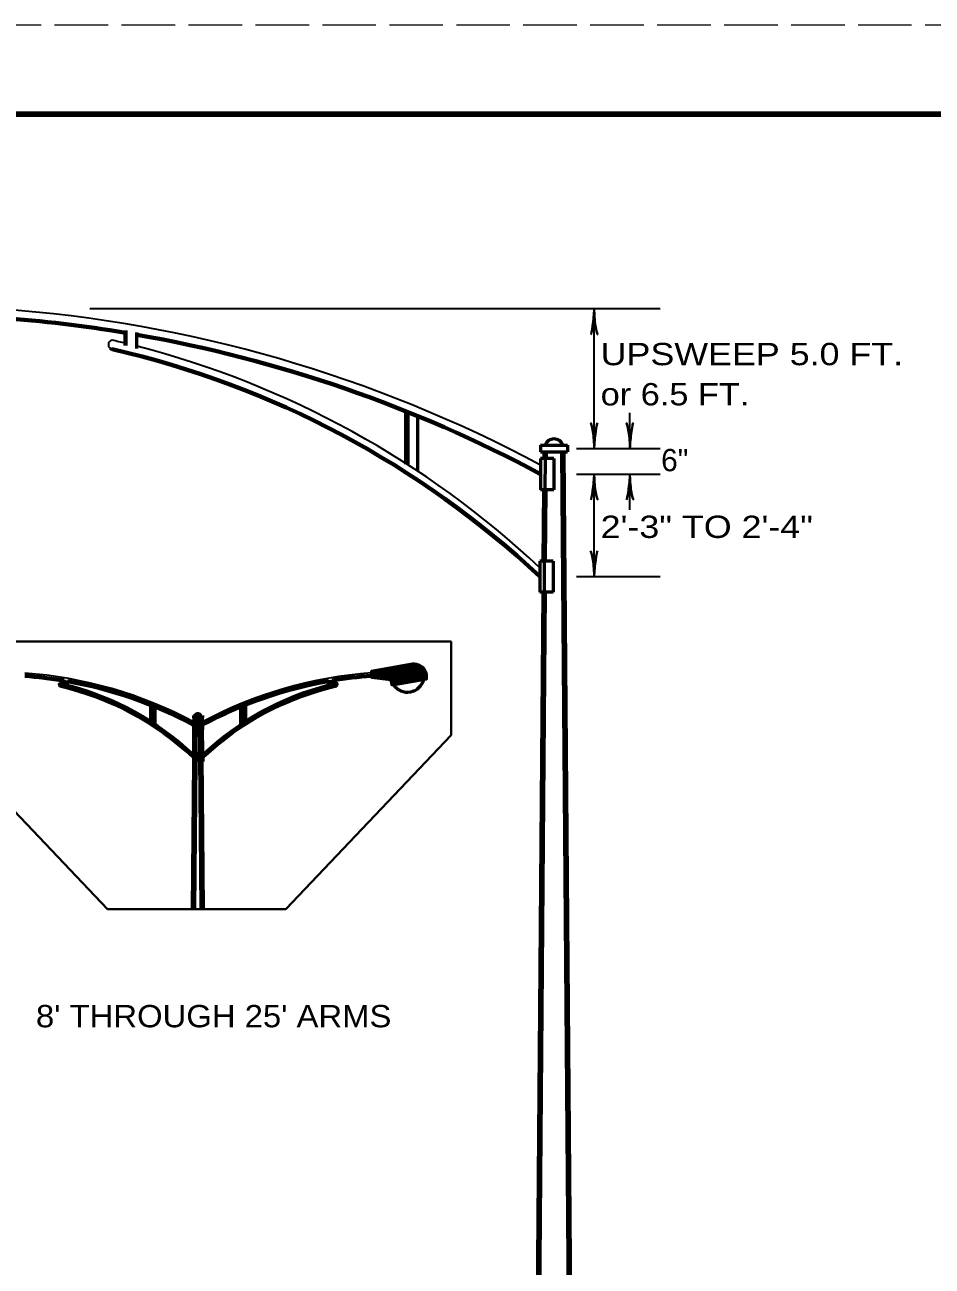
# Model space of a CAD drawing. Extents: x -1 to 679, y 1 to 441.
# Drawn here: x 78.6 to 180.2, y 301.7 to 440.9 of the extents above; entities that cross this region are included whole.
import ezdxf

# ---------------------------------------------------------------- set-up
doc = ezdxf.new("R2010")
doc.units = 0
doc.linetypes.add('LONG_DASHED', pattern=[7.5, 6, -1.5])
doc.layers.add('1', color=7, linetype='Continuous', lineweight=13)
doc.layers.add('61', color=7, linetype='Continuous', lineweight=35)

msp = doc.modelspace()

# ---------------------------------------------------------------- linework, layer by layer
at = {"layer": '1', "lineweight": 35}
for p, q in [((149.714, 409.017), (85.835, 409.017)), ((142.335, 393.392), (142.335, 409.017)), ((146.335, 393.392), (146.335, 397.392)), ((140.335, 393.392), (149.714, 393.392)), ((140.335, 390.517), (149.714, 390.517)), ((142.335, 379.017), (142.335, 390.517)), ((146.335, 386.517), (146.335, 390.517)), ((140.335, 379.017), (149.714, 379.017))]:
    msp.add_line(p, q, dxfattribs=at)
at = {"layer": '1', "lineweight": 70}
for p, q in [((89.835, 404.912), (89.835, 406.601)), ((82.932, 366.924), (82.932, 367.452)), ((113.005, 366.939), (113.005, 367.467))]:
    msp.add_line(p, q, dxfattribs=at)
at = {"layer": '1', "lineweight": 53}
for p, q in [((91.085, 404.598), (91.085, 406.388)), ((122.585, 390.824), (122.585, 397.006)), ((136.335, 393.767), (139.335, 393.767)), ((136.335, 393.767), (136.335, 393.017)), ((139.335, 393.767), (139.335, 393.017)), ((136.335, 393.017), (139.335, 393.017)), ((137.829, 392.267), (136.329, 392.267)), ((136.329, 392.267), (136.329, 388.767)), ((136.829, 392.267), (136.803, 388.767)), ((137.829, 392.267), (137.829, 388.767)), ((137.829, 388.767), (136.329, 388.767)), ((137.742, 380.767), (136.242, 380.767)), ((136.242, 380.767), (136.242, 377.267)), ((136.742, 380.767), (136.716, 377.267)), ((137.742, 380.767), (137.742, 377.267)), ((137.742, 377.267), (136.242, 377.267)), ((119.603, 368.261), (119.17, 368.694)), ((119.647, 368.261), (119.208, 368.701)), ((119.692, 368.261), (119.245, 368.707)), ((119.736, 368.261), (119.283, 368.714)), ((119.78, 368.261), (119.321, 368.721)), ((119.824, 368.261), (119.358, 368.727)), ((119.868, 368.261), (119.396, 368.734)), ((119.913, 368.261), (119.433, 368.74)), ((119.957, 368.261), (119.471, 368.747)), ((120.001, 368.261), (119.508, 368.754)), ((120.045, 368.261), (119.546, 368.76)), ((120.089, 368.261), (119.584, 368.767)), ((120.134, 368.261), (119.621, 368.774)), ((120.178, 368.261), (119.659, 368.78)), ((120.222, 368.261), (119.696, 368.787)), ((120.266, 368.261), (119.734, 368.793)), ((120.31, 368.261), (119.771, 368.8)), ((120.355, 368.261), (119.809, 368.807)), ((120.399, 368.261), (119.847, 368.813)), ((120.443, 368.261), (119.884, 368.82)), ((120.487, 368.261), (119.922, 368.826)), ((120.531, 368.261), (119.959, 368.833)), ((120.576, 368.261), (119.997, 368.84)), ((120.62, 368.261), (120.034, 368.846)), ((120.664, 368.261), (120.072, 368.853)), ((120.708, 368.261), (120.11, 368.86)), ((120.752, 368.261), (120.147, 368.866)), ((120.796, 368.261), (120.185, 368.873)), ((120.841, 368.261), (120.222, 368.879)), ((120.885, 368.261), (120.26, 368.886)), ((120.929, 368.261), (120.297, 368.893)), ((120.973, 368.261), (120.335, 368.899)), ((121.017, 368.261), (120.373, 368.906)), ((121.062, 368.261), (120.41, 368.913)), ((121.106, 368.261), (120.448, 368.919)), ((121.15, 368.261), (120.485, 368.926)), ((121.194, 368.261), (120.523, 368.933)), ((121.239, 368.261), (120.56, 368.939)), ((121.283, 368.261), (120.598, 368.946)), ((121.327, 368.261), (120.636, 368.952)), ((121.371, 368.261), (120.673, 368.959)), ((121.415, 368.261), (120.711, 368.966)), ((121.459, 368.261), (120.748, 368.972)), ((121.504, 368.261), (120.786, 368.979)), ((121.548, 368.261), (120.823, 368.986)), ((121.592, 368.261), (120.861, 368.992)), ((121.636, 368.261), (120.899, 368.999)), ((121.68, 368.261), (120.936, 369.005)), ((121.725, 368.261), (120.974, 369.012)), ((121.769, 368.261), (121.011, 369.019)), ((121.813, 368.261), (121.049, 369.025)), ((121.857, 368.261), (121.086, 369.032)), ((121.901, 368.261), (121.124, 369.038)), ((121.946, 368.261), (121.161, 369.045)), ((121.99, 368.261), (121.199, 369.052)), ((122.034, 368.261), (121.237, 369.058)), ((122.078, 368.261), (121.274, 369.065)), ((122.122, 368.261), (121.312, 369.072)), ((122.167, 368.261), (121.349, 369.078)), ((122.211, 368.261), (121.387, 369.085)), ((122.255, 368.261), (121.424, 369.091)), ((122.299, 368.261), (121.462, 369.098)), ((122.343, 368.261), (121.5, 369.105)), ((122.388, 368.261), (121.537, 369.111)), ((122.432, 368.261), (121.575, 369.118)), ((122.476, 368.261), (121.612, 369.125)), ((122.52, 368.261), (121.65, 369.131)), ((122.564, 368.261), (121.688, 369.138)), ((122.608, 368.261), (121.725, 369.144)), ((122.653, 368.261), (121.763, 369.151)), ((122.697, 368.261), (121.8, 369.158)), ((122.741, 368.261), (121.838, 369.164)), ((122.785, 368.261), (121.875, 369.171)), ((122.829, 368.261), (121.913, 369.178)), ((122.874, 368.261), (121.95, 369.184)), ((122.918, 368.261), (121.988, 369.191)), ((122.962, 368.261), (122.028, 369.195)), ((123.006, 368.261), (122.07, 369.197)), ((123.05, 368.261), (122.114, 369.197)), ((123.095, 368.261), (122.158, 369.198)), ((123.139, 368.261), (122.202, 369.198)), ((123.183, 368.261), (122.251, 369.193)), ((123.227, 368.261), (122.299, 369.189)), ((123.271, 368.261), (122.349, 369.184)), ((123.316, 368.261), (122.404, 369.173)), ((123.529, 368.091), (122.459, 369.162)), ((123.517, 368.148), (122.518, 369.147)), ((123.495, 368.214), (122.582, 369.127)), ((123.473, 368.28), (122.648, 369.105)), ((123.439, 368.358), (122.726, 369.071)), ((123.4, 368.442), (122.813, 369.029)), ((123.336, 368.55), (122.919, 368.966)), ((123.139, 368.791), (123.138, 368.792)), ((83.323, 366.826), (83.323, 367.385)), ((112.614, 366.841), (112.614, 367.4)), ((117.536, 368.207), (117.38, 368.363)), ((118.025, 367.674), (117.38, 368.319)), ((117.974, 367.68), (117.38, 368.275)), ((117.924, 367.686), (117.38, 368.231)), ((117.874, 367.693), (117.38, 368.187)), ((117.823, 367.699), (117.38, 368.142)), ((117.773, 367.705), (117.38, 368.098)), ((117.722, 367.711), (117.38, 368.054)), ((117.672, 367.717), (117.38, 368.01)), ((117.622, 367.724), (117.38, 367.966)), ((117.571, 367.73), (117.38, 367.921)), ((117.521, 367.736), (117.38, 367.877)), ((117.471, 367.742), (117.38, 367.833)), ((117.42, 367.748), (117.38, 367.789)), ((117.536, 368.251), (117.405, 368.383)), ((117.57, 368.261), (117.442, 368.389)), ((117.614, 368.261), (117.48, 368.396)), ((117.659, 368.261), (117.517, 368.402)), ((117.703, 368.261), (117.555, 368.409)), ((118.075, 367.668), (117.56, 368.183)), ((117.747, 368.261), (117.592, 368.416)), ((118.126, 367.662), (117.604, 368.183)), ((117.791, 368.261), (117.63, 368.422)), ((118.176, 367.655), (117.648, 368.183)), ((117.836, 368.261), (117.667, 368.429)), ((118.226, 367.649), (117.693, 368.183)), ((117.88, 368.261), (117.705, 368.436)), ((118.277, 367.643), (117.737, 368.183)), ((117.924, 368.261), (117.743, 368.442)), ((117.968, 368.261), (117.78, 368.449)), ((118.327, 367.637), (117.781, 368.183)), ((118.012, 368.261), (117.818, 368.455)), ((118.377, 367.631), (117.825, 368.183)), ((118.056, 368.261), (117.855, 368.462)), ((118.428, 367.625), (117.869, 368.183)), ((118.101, 368.261), (117.893, 368.469)), ((118.478, 367.618), (117.914, 368.183)), ((118.145, 368.261), (117.931, 368.475)), ((118.529, 367.612), (117.958, 368.183)), ((118.189, 368.261), (117.968, 368.482)), ((118.579, 367.606), (118.002, 368.183)), ((118.233, 368.261), (118.006, 368.489)), ((118.277, 368.261), (118.043, 368.495)), ((118.629, 367.6), (118.046, 368.183)), ((118.322, 368.261), (118.081, 368.502)), ((118.68, 367.594), (118.09, 368.183)), ((118.366, 368.261), (118.118, 368.508)), ((118.73, 367.587), (118.135, 368.183)), ((118.41, 368.261), (118.156, 368.515)), ((118.78, 367.581), (118.179, 368.183)), ((118.454, 368.261), (118.194, 368.522)), ((118.831, 367.575), (118.223, 368.183)), ((118.498, 368.261), (118.231, 368.528)), ((118.881, 367.569), (118.267, 368.183)), ((118.543, 368.261), (118.269, 368.535)), ((118.587, 368.261), (118.306, 368.542)), ((118.932, 367.563), (118.311, 368.183)), ((118.631, 368.261), (118.344, 368.548)), ((118.982, 367.556), (118.356, 368.183)), ((118.675, 368.261), (118.381, 368.555)), ((119.032, 367.55), (118.4, 368.183)), ((118.719, 368.261), (118.419, 368.561)), ((119.083, 367.544), (118.444, 368.183)), ((118.764, 368.261), (118.456, 368.568)), ((119.133, 367.538), (118.488, 368.183)), ((118.808, 368.261), (118.494, 368.575)), ((118.852, 368.261), (118.532, 368.581)), ((119.184, 367.532), (118.532, 368.183)), ((118.896, 368.261), (118.569, 368.588)), ((119.234, 367.525), (118.577, 368.183)), ((118.94, 368.261), (118.607, 368.595)), ((119.284, 367.519), (118.621, 368.183)), ((118.984, 368.261), (118.644, 368.601)), ((119.335, 367.513), (118.665, 368.183)), ((119.029, 368.261), (118.682, 368.608)), ((119.385, 367.507), (118.709, 368.183)), ((119.073, 368.261), (118.719, 368.614)), ((119.435, 367.501), (118.753, 368.183)), ((119.117, 368.261), (118.757, 368.621)), ((119.161, 368.261), (118.795, 368.628)), ((119.486, 367.495), (118.797, 368.183)), ((119.206, 368.261), (118.832, 368.634)), ((119.536, 367.488), (118.842, 368.183)), ((119.25, 368.261), (118.87, 368.641)), ((120.113, 366.956), (118.886, 368.183)), ((119.294, 368.261), (118.907, 368.648)), ((120.15, 366.963), (118.93, 368.183)), ((119.338, 368.261), (118.945, 368.654)), ((120.188, 366.969), (118.974, 368.183)), ((119.382, 368.261), (118.983, 368.661)), ((120.225, 366.976), (119.019, 368.183)), ((119.426, 368.261), (119.02, 368.667)), ((119.471, 368.261), (119.058, 368.674)), ((120.263, 366.983), (119.063, 368.183)), ((119.515, 368.261), (119.095, 368.681)), ((120.301, 366.989), (119.107, 368.183)), ((119.559, 368.261), (119.133, 368.687)), ((120.338, 366.996), (119.151, 368.183)), ((120.376, 367.003), (119.195, 368.183)), ((120.413, 367.009), (119.239, 368.183)), ((120.451, 367.016), (119.284, 368.183)), ((120.488, 367.022), (119.328, 368.183)), ((120.526, 367.029), (119.372, 368.183)), ((120.563, 367.036), (119.416, 368.183)), ((120.601, 367.042), (119.46, 368.183)), ((120.639, 367.049), (119.505, 368.183)), ((120.676, 367.055), (119.549, 368.183)), ((120.075, 366.95), (119.555, 367.47)), ((120.037, 366.943), (119.568, 367.412)), ((120, 366.936), (119.581, 367.355)), ((120.714, 367.062), (119.593, 368.183)), ((119.962, 366.93), (119.594, 367.298)), ((120.751, 367.069), (119.637, 368.183)), ((120.789, 367.075), (119.681, 368.183)), ((120.826, 367.082), (119.726, 368.183)), ((120.864, 367.089), (119.77, 368.183)), ((120.902, 367.095), (119.814, 368.183)), ((120.939, 367.102), (119.858, 368.183)), ((120.977, 367.108), (119.902, 368.183)), ((121.014, 367.115), (119.947, 368.183)), ((121.052, 367.122), (119.991, 368.183)), ((121.089, 367.128), (120.035, 368.183)), ((121.127, 367.135), (120.079, 368.183)), ((121.165, 367.142), (120.123, 368.183)), ((121.202, 367.148), (120.167, 368.183)), ((121.24, 367.155), (120.212, 368.183)), ((121.277, 367.161), (120.256, 368.183)), ((121.315, 367.168), (120.3, 368.183)), ((121.352, 367.175), (120.344, 368.183)), ((121.39, 367.181), (120.388, 368.183)), ((121.427, 367.188), (120.433, 368.183)), ((121.465, 367.195), (120.477, 368.183)), ((121.503, 367.201), (120.521, 368.183)), ((121.54, 367.208), (120.565, 368.183)), ((121.578, 367.215), (120.609, 368.183)), ((121.615, 367.221), (120.654, 368.183)), ((121.653, 367.228), (120.698, 368.183)), ((121.691, 367.234), (120.742, 368.183)), ((121.728, 367.241), (120.786, 368.183)), ((121.766, 367.248), (120.83, 368.183)), ((121.803, 367.254), (120.875, 368.183)), ((121.841, 367.261), (120.919, 368.183)), ((121.878, 367.268), (120.963, 368.183)), ((121.916, 367.274), (121.007, 368.183)), ((121.954, 367.281), (121.051, 368.183)), ((121.991, 367.287), (121.096, 368.183)), ((122.029, 367.294), (121.14, 368.183)), ((122.066, 367.301), (121.184, 368.183)), ((122.104, 367.307), (121.228, 368.183)), ((122.141, 367.314), (121.272, 368.183)), ((122.179, 367.32), (121.317, 368.183)), ((122.216, 367.327), (121.361, 368.183)), ((122.254, 367.334), (121.405, 368.183)), ((122.292, 367.34), (121.449, 368.183)), ((122.329, 367.347), (121.493, 368.183)), ((122.367, 367.354), (121.537, 368.183)), ((122.404, 367.36), (121.582, 368.183)), ((122.442, 367.367), (121.626, 368.183)), ((122.48, 367.373), (121.67, 368.183)), ((122.517, 367.38), (121.714, 368.183)), ((122.555, 367.387), (121.759, 368.183)), ((122.592, 367.393), (121.803, 368.183)), ((122.63, 367.4), (121.847, 368.183)), ((122.667, 367.407), (121.891, 368.183)), ((122.705, 367.413), (121.935, 368.183)), ((122.742, 367.42), (121.98, 368.183)), ((122.78, 367.426), (122.024, 368.183)), ((122.818, 367.433), (122.068, 368.183)), ((122.855, 367.44), (122.112, 368.183)), ((122.893, 367.446), (122.156, 368.183)), ((122.93, 367.453), (122.2, 368.183)), ((122.968, 367.46), (122.245, 368.183)), ((123.005, 367.466), (122.289, 368.183)), ((123.043, 367.473), (122.333, 368.183)), ((123.081, 367.48), (122.377, 368.183)), ((123.118, 367.486), (122.421, 368.183)), ((123.156, 367.493), (122.466, 368.183)), ((123.193, 367.499), (122.51, 368.183)), ((123.231, 367.506), (122.554, 368.183)), ((123.268, 367.513), (122.598, 368.183)), ((123.306, 367.519), (122.642, 368.183)), ((123.344, 367.526), (122.687, 368.183)), ((123.381, 367.533), (122.731, 368.183)), ((123.419, 367.539), (122.775, 368.183)), ((123.456, 367.546), (122.819, 368.183)), ((123.494, 367.552), (122.863, 368.183)), ((123.531, 367.559), (122.907, 368.183)), ((123.554, 367.58), (122.952, 368.183)), ((123.558, 367.621), (122.996, 368.183)), ((123.562, 367.661), (123.04, 368.183)), ((123.566, 367.702), (123.084, 368.183)), ((123.566, 367.745), (123.129, 368.183)), ((123.566, 367.79), (123.173, 368.183)), ((123.565, 367.835), (123.217, 368.183)), ((123.562, 367.881), (123.261, 368.183)), ((123.557, 367.931), (123.305, 368.183)), ((123.542, 368.035), (123.325, 368.252)), ((123.551, 367.981), (123.325, 368.208)), ((119.925, 366.923), (119.608, 367.24)), ((119.887, 366.916), (119.621, 367.183)), ((119.85, 366.91), (119.634, 367.125)), ((119.812, 366.903), (119.647, 367.068)), ((119.774, 366.897), (119.661, 367.01)), ((119.737, 366.89), (119.674, 366.953)), ((119.699, 366.883), (119.687, 366.895)), ((93.167, 362.521), (93.167, 364.453)), ((97.464, 363.441), (98.401, 363.441)), ((97.464, 363.441), (97.464, 363.207)), ((97.464, 363.207), (98.401, 363.207)), ((98.401, 363.441), (98.401, 363.207)), ((98.473, 363.456), (98.473, 363.222)), ((102.77, 362.537), (102.77, 364.469)), ((97.931, 362.972), (97.462, 362.972)), ((97.462, 362.972), (97.462, 361.879)), ((97.931, 361.879), (97.462, 361.879)), ((97.618, 362.972), (97.61, 361.879)), ((97.931, 362.972), (97.931, 361.879)), ((98.006, 362.988), (98.475, 362.988)), ((98.006, 362.988), (98.006, 361.894)), ((98.006, 361.894), (98.475, 361.894)), ((98.319, 362.988), (98.327, 361.894)), ((98.475, 362.988), (98.475, 361.894)), ((97.903, 359.379), (97.435, 359.379)), ((97.435, 359.379), (97.435, 358.285)), ((97.591, 359.379), (97.582, 358.285)), ((97.903, 359.379), (97.903, 358.285)), ((98.034, 359.394), (98.502, 359.394)), ((98.034, 359.394), (98.034, 358.3)), ((98.346, 359.394), (98.354, 358.3)), ((98.502, 359.394), (98.502, 358.3)), ((97.903, 358.285), (97.435, 358.285)), ((98.034, 358.3), (98.502, 358.3))]:
    msp.add_line(p, q, dxfattribs=at)
at = {"layer": '1', "lineweight": 90}
for p, q in [((121.335, 391.64), (121.335, 397.515)), ((136.835, 393.017), (136.829, 392.267)), ((139.835, 261.017), (138.835, 393.017)), ((136.803, 388.767), (136.742, 380.767)), ((136.716, 377.267), (135.835, 261.017)), ((92.776, 362.776), (92.776, 364.612)), ((103.161, 362.792), (103.161, 364.628)), ((97.62, 363.207), (97.618, 362.972)), ((98.407, 341.767), (98.245, 363.207)), ((98.317, 363.222), (98.319, 362.988)), ((97.61, 361.879), (97.591, 359.379)), ((98.327, 361.894), (98.346, 359.394)), ((97.583, 358.285), (97.457, 341.767))]:
    msp.add_line(p, q, dxfattribs=at)
at = {"layer": '1', "lineweight": 40}
for p, q in [((126.301, 371.767), (69.301, 371.767)), ((126.301, 371.767), (126.301, 361.267)), ((69.301, 361.267), (87.801, 341.767)), ((126.301, 361.267), (107.801, 341.767)), ((107.801, 341.767), (87.801, 341.767))]:
    msp.add_line(p, q, dxfattribs=at)
at = {"layer": '1', "lineweight": 53}
msp.add_lwpolyline([(121.996, 369.192), (117.38, 368.378), (117.38, 367.753), (119.551, 367.487), (119.69, 366.882), (123.552, 367.563), (123.552, 367.563)], dxfattribs=at)
at = {"layer": '1'}
msp.add_lwpolyline([(123.325, 368.261), (117.536, 368.261), (117.536, 368.183), (123.325, 368.183)], close=True, dxfattribs=at)
at = {"layer": '1', "lineweight": 35}
for centre, radius, start, end in [((64.993, 258.23), 151.176, 61.84402, 85.88743), ((88.418, 405.017), 0.507, 99.37484, 260.62516), ((65.152, 304.21), 103.926, 76.2603, 77.11012), ((65.152, 304.21), 103.926, 46.83897, 75.54976), ((75.169, 321.086), 47.243, 61.84402, 85.88743), ((120.768, 321.101), 47.243, 94.11257, 118.15598), ((82.489, 366.957), 0.158, 99.37484, 260.62516), ((75.219, 335.454), 32.477, 76.2603, 77.11012), ((75.219, 335.454), 32.477, 46.83897, 75.54976), ((120.718, 335.47), 32.477, 104.45024, 133.16103), ((120.718, 335.47), 32.477, 102.88988, 103.7397), ((113.448, 366.972), 0.158, 279.37484, 80.62516)]:
    msp.add_arc(centre, radius, start, end, dxfattribs=at)
at = {"layer": '1', "lineweight": 70}
for centre, radius, start, end in [((64.993, 257.23), 151.176, 80.54208, 85.88743), ((64.993, 257.23), 151.176, 61.84402, 80.06146), ((65.152, 303.21), 103.926, 46.83897, 77.11012), ((75.169, 320.773), 47.243, 80.54208, 85.88743), ((75.169, 320.773), 47.243, 61.84402, 80.06146), ((120.768, 320.788), 47.243, 99.93854, 118.15598), ((120.768, 320.788), 47.243, 94.11257, 99.45792), ((75.219, 335.142), 32.477, 46.83897, 77.11012), ((120.718, 335.157), 32.477, 102.88988, 133.16103)]:
    msp.add_arc(centre, radius, start, end, dxfattribs=at)
at = {"layer": '1', "lineweight": 53}
for centre, radius, start, end in [((88.567, 405.347), 0.861, 235.53017, 254.38288), ((137.835, 393.397), 1.061, 20.3922, 159.6078), ((122.139, 367.771), 1.429, 351.61838, 95.76047), ((121.411, 367.964), 1.889, 213.94941, 346.05238), ((82.536, 367.06), 0.269, 235.53017, 254.38288), ((113.401, 367.075), 0.269, 285.61712, 304.46983), ((97.932, 363.326), 0.332, 20.3922, 159.6078)]:
    msp.add_arc(centre, radius, start, end, dxfattribs=at)
at = {"layer": '1', "lineweight": 40}
for centre, major_axis, ratio, start_param, end_param in [((142.124, 407.897), (0.176, 1.756), 0.07063, 3.1407148, 5.41811), ((142.124, 407.897), (0.176, 1.756), 0.07063, 3.1407148, 5.41811), ((142.612, 407.926), (-0.156, 1.786), 0.122415, 0.8963533, 3.1415927), ((142.612, 407.926), (-0.156, 1.786), 0.122415, 0.8963533, 3.1415927), ((142.059, 394.483), (0.156, -1.786), 0.122415, 0.8963533, 3.1415927), ((142.059, 394.483), (0.156, -1.786), 0.122415, 0.8963533, 3.1415927), ((142.547, 394.513), (-0.176, -1.756), 0.07063, 3.1407148, 5.41811), ((142.547, 394.513), (-0.176, -1.756), 0.07063, 3.1407148, 5.41811), ((146.059, 394.483), (0.156, -1.786), 0.122415, 0.8963533, 3.1415927), ((146.059, 394.483), (0.156, -1.786), 0.122415, 0.8963533, 3.1415927), ((146.547, 394.513), (-0.176, -1.756), 0.07063, 3.1407148, 5.41811), ((146.547, 394.513), (-0.176, -1.756), 0.07063, 3.1407148, 5.41811), ((142.124, 389.397), (0.176, 1.756), 0.07063, 3.1407148, 5.41811), ((142.124, 389.397), (0.176, 1.756), 0.07063, 3.1407148, 5.41811), ((142.612, 389.426), (-0.156, 1.786), 0.122415, 0.8963533, 3.1415927), ((142.612, 389.426), (-0.156, 1.786), 0.122415, 0.8963533, 3.1415927), ((146.124, 389.397), (0.176, 1.756), 0.07063, 3.1407148, 5.41811), ((146.124, 389.397), (0.176, 1.756), 0.07063, 3.1407148, 5.41811), ((146.612, 389.426), (-0.156, 1.786), 0.122415, 0.8963533, 3.1415927), ((146.612, 389.426), (-0.156, 1.786), 0.122415, 0.8963533, 3.1415927), ((142.059, 380.108), (0.156, -1.786), 0.122415, 0.8963533, 3.1415927), ((142.059, 380.108), (0.156, -1.786), 0.122415, 0.8963533, 3.1415927), ((142.547, 380.138), (-0.176, -1.756), 0.07063, 3.1407148, 5.41811), ((142.547, 380.138), (-0.176, -1.756), 0.07063, 3.1407148, 5.41811)]:
    msp.add_ellipse(centre, major_axis=major_axis, ratio=ratio, start_param=start_param, end_param=end_param, dxfattribs=at)
at = {"layer": '61', "linetype": 'LONG_DASHED', "lineweight": 13}
msp.add_line((-0.608, 440.866), (679.412, 440.866), dxfattribs=at)
at = {"layer": '61', "lineweight": 158}
msp.add_lwpolyline([(668.432, 430.866), (29.392, 430.866), (29.392, 10.846)], dxfattribs=at)

# ---------------------------------------------------------------- texts
at = {"layer": '1'}
for s, width, p in [('UPSWEEP 5.0 FT.', 1.2, (143.06, 402.716)), ('or 6.5 FT.', 1.15, (143.06, 398.216)), ('2\'-3" TO 2\'-4"', 1.2, (143.06, 383.356)), ("8' THROUGH 25' ARMS", 1.1, (79.801, 328.513))]:
    msp.add_text(s, height=2.5, dxfattribs=dict(at, width=width)).set_placement(p)
msp.add_text('6"', height=2.5, dxfattribs=at).set_placement((149.833, 390.834))

doc.saveas('drawing.dxf')
